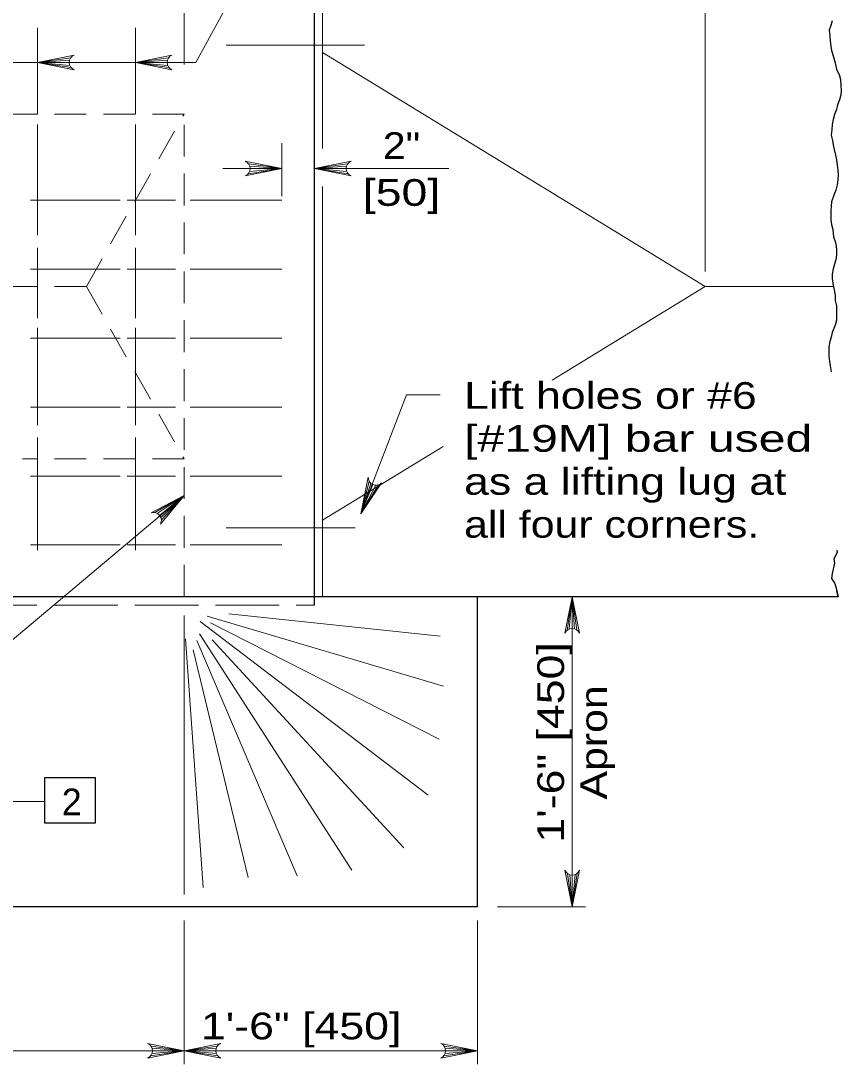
# Model space of a CAD drawing. Extents: x 339.1 to 373.1, y 1412.7 to 1456.7.
# Drawn here: x 356.2 to 360.99, y 1446.83 to 1452.93 of the extents above; entities that cross this region are included whole.
import ezdxf
from ezdxf.enums import TextEntityAlignment as Align

# ---------------------------------------------------------------- set-up
doc = ezdxf.new("R2010")
doc.units = 0
doc.header["$LTSCALE"] = 0.062
doc.linetypes.add('LONG_DASHED', pattern=[7.5, 6, -1.5])
doc.linetypes.add('MEDIUM_DASHED', pattern=[4.5, 3, -1.5])
doc.layers.add('1', color=7, linetype='Continuous', lineweight=13)

msp = doc.modelspace()

# ---------------------------------------------------------------- linework, layer by layer
at = {"layer": '1'}
for p, q in [((357.15083, 1452.67717), (357.15083, 1454.9895)), ((360.19683, 1451.46717), (360.19683, 1454.9895)), ((357.95992, 1452.18633), (357.95992, 1453.1925)), ((356.29417, 1452.38633), (356.29417, 1452.89025)), ((356.86533, 1452.38633), (356.86533, 1452.89025)), ((357.39633, 1452.78942), (358.20542, 1452.78942)), ((356.48808, 1452.71575), (356.29417, 1452.68867)), ((356.4815, 1452.70233), (356.29417, 1452.68867)), ((357.05917, 1452.71575), (356.86533, 1452.68867)), ((357.05258, 1452.70233), (356.86533, 1452.68867)), ((359.76317, 1451.64367), (357.95992, 1452.74608)), ((356.4795, 1452.68867), (356.29417, 1452.68867)), ((356.48292, 1452.67125), (356.29417, 1452.68867)), ((356.49033, 1452.65867), (356.29417, 1452.68867)), ((357.05058, 1452.68867), (356.86533, 1452.68867)), ((357.05408, 1452.67125), (356.86533, 1452.68867)), ((357.0615, 1452.65867), (356.86533, 1452.68867)), ((356.29417, 1451.67858), (356.29417, 1452.32525)), ((356.86533, 1451.67858), (356.86533, 1452.32525)), ((357.722, 1451.90667), (357.722, 1452.2175)), ((357.52808, 1452.09525), (357.722, 1452.06808)), ((357.53467, 1452.08183), (357.722, 1452.06808)), ((358.10625, 1452.09525), (357.91233, 1452.06808)), ((358.09967, 1452.08183), (357.91233, 1452.06808)), ((357.37617, 1452.06808), (357.722, 1452.06808)), ((357.52583, 1452.03808), (357.722, 1452.06808)), ((357.53325, 1452.05067), (357.722, 1452.06808)), ((357.53667, 1452.06808), (357.722, 1452.06808)), ((357.91233, 1452.06808), (358.69775, 1452.06808)), ((358.09767, 1452.06808), (357.91233, 1452.06808)), ((358.10108, 1452.05067), (357.91233, 1452.06808)), ((358.1085, 1452.03808), (357.91233, 1452.06808)), ((357.95992, 1449.56467), (357.95992, 1451.964)), ((356.77733, 1451.88242), (356.2535, 1451.88242)), ((357.09992, 1451.88242), (356.81767, 1451.88242)), ((357.18508, 1451.88242), (357.722, 1451.88242)), ((356.29417, 1451.19358), (356.29417, 1451.6055)), ((356.86533, 1451.19358), (356.86533, 1451.6055)), ((360.19683, 1451.37858), (359.76317, 1451.64367)), ((356.77733, 1451.47933), (356.2535, 1451.47933)), ((357.09992, 1451.47933), (356.81767, 1451.47933)), ((357.18508, 1451.47933), (357.722, 1451.47933)), ((360.19683, 1451.37858), (359.76008, 1451.11158)), ((360.19683, 1451.37858), (360.94533, 1451.37858)), ((356.29417, 1450.56767), (356.29417, 1451.13608)), ((356.86533, 1450.56767), (356.86533, 1451.13608)), ((359.76008, 1451.11158), (359.30133, 1450.83092)), ((356.77733, 1451.07625), (356.2535, 1451.07625)), ((357.09992, 1451.07625), (356.81767, 1451.07625)), ((357.18508, 1451.07625), (357.722, 1451.07625)), ((356.77733, 1450.67317), (356.2535, 1450.67317)), ((357.09992, 1450.67317), (356.81767, 1450.67317)), ((357.18508, 1450.67317), (357.722, 1450.67317)), ((356.29417, 1449.8375), (356.29417, 1450.49467)), ((356.86533, 1449.8375), (356.86533, 1450.49467)), ((358.66542, 1450.44242), (357.95992, 1450.01133)), ((356.77733, 1450.27008), (356.2535, 1450.27008)), ((357.09992, 1450.27008), (356.81767, 1450.27008)), ((357.18508, 1450.27008), (357.722, 1450.27008)), ((358.23217, 1450.23808), (358.1825, 1450.04875)), ((358.242, 1450.22692), (358.1825, 1450.04875)), ((358.25392, 1450.21975), (358.1825, 1450.04875)), ((358.28575, 1450.21825), (358.1825, 1450.04875)), ((358.27125, 1450.21625), (358.1825, 1450.04875)), ((356.97983, 1450.05625), (357.15083, 1450.157)), ((356.99358, 1450.05125), (357.15083, 1450.157)), ((357.00717, 1450.03992), (357.15083, 1450.157)), ((357.01433, 1450.028), (357.15083, 1450.157)), ((357.01775, 1450.01342), (357.15083, 1450.157)), ((356.77733, 1449.86692), (356.2535, 1449.86692)), ((357.09992, 1449.86692), (356.81767, 1449.86692)), ((357.18508, 1449.86692), (357.722, 1449.86692)), ((359.38842, 1449.36842), (359.41842, 1449.56467)), ((359.401, 1449.37583), (359.41842, 1449.56467)), ((359.41842, 1447.75067), (359.41842, 1449.56467)), ((359.41842, 1449.37933), (359.41842, 1449.56467)), ((359.43208, 1449.37733), (359.41842, 1449.56467)), ((359.4455, 1449.37075), (359.41842, 1449.56467)), ((358.64683, 1449.33425), (357.41192, 1449.46475)), ((357.15083, 1447.82367), (357.15083, 1449.45425)), ((358.57633, 1448.40492), (357.24375, 1449.41883)), ((358.66667, 1449.04042), (357.28467, 1449.45167)), ((358.64075, 1448.73142), (357.30383, 1449.41267)), ((357.23967, 1449.34808), (358.13033, 1447.96567)), ((357.15875, 1449.31792), (357.26192, 1447.86433)), ((357.225, 1449.30858), (357.81183, 1447.93217)), ((357.31367, 1449.31142), (358.43408, 1448.096)), ((357.20367, 1449.25483), (357.52425, 1447.92333)), ((359.39125, 1447.94458), (359.41842, 1447.75067)), ((359.40467, 1447.938), (359.41842, 1447.75067)), ((359.44842, 1447.94683), (359.41842, 1447.75067)), ((359.43583, 1447.93942), (359.41842, 1447.75067)), ((359.41842, 1447.936), (359.41842, 1447.75067)), ((358.98208, 1447.75067), (359.49708, 1447.75067)), ((357.15083, 1447.67167), (357.15083, 1446.83117)), ((358.86425, 1447.67167), (358.86425, 1446.83117)), ((356.95467, 1446.87983), (357.15083, 1446.90983)), ((356.957, 1446.937), (357.15083, 1446.90983)), ((356.96208, 1446.89242), (357.15083, 1446.90983)), ((356.9635, 1446.92358), (357.15083, 1446.90983)), ((356.9655, 1446.90983), (357.15083, 1446.90983)), ((357.34475, 1446.937), (357.15083, 1446.90983)), ((357.33817, 1446.92358), (357.15083, 1446.90983)), ((358.86425, 1446.90983), (357.15083, 1446.90983)), ((357.33617, 1446.90983), (357.15083, 1446.90983)), ((357.33958, 1446.89242), (357.15083, 1446.90983)), ((357.347, 1446.87983), (357.15083, 1446.90983)), ((358.668, 1446.87983), (358.86425, 1446.90983)), ((358.67033, 1446.937), (358.86425, 1446.90983)), ((358.6755, 1446.89242), (358.86425, 1446.90983)), ((358.67692, 1446.92358), (358.86425, 1446.90983)), ((358.67892, 1446.90983), (358.86425, 1446.90983))]:
    msp.add_line(p, q, dxfattribs=at)
at = {"layer": '1', "linetype": 'MEDIUM_DASHED'}
for p, q in [((357.15083, 1452.38633), (345.68083, 1452.38633)), ((356.57975, 1451.37858), (357.15083, 1452.38633)), ((357.15083, 1449.56467), (357.15083, 1452.38633)), ((356.57975, 1451.37858), (353.80425, 1451.37858)), ((356.57975, 1451.37858), (357.15083, 1450.37083)), ((357.15083, 1450.37083), (356.20625, 1450.37083))]:
    msp.add_line(p, q, dxfattribs=at)
at = {"layer": '1', "lineweight": 25}
for p, q in [((360.97275, 1449.56467), (343.61608, 1449.56467)), ((358.86425, 1447.75067), (358.86425, 1449.56467)), ((358.86425, 1447.75067), (353.90383, 1447.75067))]:
    msp.add_line(p, q, dxfattribs=at)
at = {"layer": '1', "linetype": 'LONG_DASHED'}
msp.add_line((345.06217, 1449.51425), (357.91233, 1449.51425), dxfattribs=at)
at = {"layer": '1'}
for points in [[(357.219, 1452.68867), (357.70825, 1453.58567), (358.31458, 1453.58567)], [(356.50833, 1452.64583), (356.29417, 1452.68867), (356.50833, 1452.7315)], [(357.0795, 1452.64583), (356.86533, 1452.68867), (357.0795, 1452.7315)], [(357.219, 1452.68867), (356.86533, 1452.68867), (356.29417, 1452.68867), (355.72308, 1452.68867)], [(357.50783, 1452.02525), (357.722, 1452.06808), (357.50783, 1452.11092)], [(358.1265, 1452.02525), (357.91233, 1452.06808), (358.1265, 1452.11092)], [(358.1825, 1450.04875), (358.45, 1450.74492), (358.64667, 1450.74492)], [(358.3045, 1450.22992), (358.1825, 1450.04875), (358.2255, 1450.26292)], [(357.15083, 1450.157), (355.54258, 1448.80458), (355.22842, 1448.80458)], [(356.95775, 1450.05483), (357.15083, 1450.157), (357.01192, 1449.98842)], [(357.39633, 1449.96775), (357.49008, 1449.96775), (358.14992, 1449.96775)], [(359.37558, 1449.3505), (359.41842, 1449.56467), (359.46125, 1449.3505)], [(355.27908, 1447.7505), (356.0625, 1448.36683), (356.33358, 1448.36683)], [(359.46125, 1447.96483), (359.41842, 1447.75067), (359.37558, 1447.96483)], [(357.15083, 1446.90983), (352.38625, 1446.90983), (345.82367, 1446.90983)], [(356.93667, 1446.867), (357.15083, 1446.90983), (356.93667, 1446.95267)], [(357.365, 1446.867), (357.15083, 1446.90983), (357.365, 1446.95267)], [(358.65008, 1446.867), (358.86425, 1446.90983), (358.65008, 1446.95267)]]:
    msp.add_lwpolyline(points, dxfattribs=at)
at = {"layer": '1', "lineweight": 25}
for points in [[(357.91233, 1449.51425), (357.91233, 1453.1925), (343.58617, 1453.1925)], [(360.93858, 1452.93225), (360.92958, 1452.904), (360.92075, 1452.87708), (360.92458, 1452.84342), (360.92583, 1452.8125), (360.92958, 1452.78433), (360.93475, 1452.75867), (360.94358, 1452.72775), (360.955, 1452.68617), (360.964, 1452.64717), (360.97917, 1452.61892), (360.98683, 1452.588), (360.98942, 1452.55567), (360.99058, 1452.52467), (360.98808, 1452.49917), (360.98175, 1452.46958), (360.969, 1452.44133), (360.96267, 1452.41442), (360.95258, 1452.3835), (360.94358, 1452.35533), (360.93733, 1452.32567), (360.936, 1452.29475), (360.93217, 1452.26392), (360.93983, 1452.23292), (360.94358, 1452.20608), (360.95, 1452.17917), (360.95758, 1452.14692), (360.964, 1452.11858), (360.96775, 1452.08908), (360.97158, 1452.05942), (360.97283, 1452.03392), (360.97158, 1452.00158), (360.96775, 1451.97208), (360.95883, 1451.94108), (360.94875, 1451.91292), (360.9335, 1451.87392), (360.93217, 1451.84833), (360.93092, 1451.82008), (360.93092, 1451.79317), (360.93092, 1451.76758), (360.93475, 1451.74067), (360.94117, 1451.71117), (360.94617, 1451.66808), (360.95633, 1451.6425), (360.96142, 1451.617), (360.96267, 1451.59142), (360.96267, 1451.56317), (360.95883, 1451.535), (360.95258, 1451.50942), (360.94358, 1451.4825), (360.93858, 1451.45158), (360.93858, 1451.42608), (360.94492, 1451.38433), (360.95, 1451.35875), (360.955, 1451.3265), (360.95633, 1451.29692), (360.96267, 1451.266), (360.964, 1451.23642), (360.964, 1451.21075), (360.964, 1451.18125), (360.95633, 1451.15167), (360.93733, 1451.11), (360.93217, 1451.08308), (360.92458, 1451.0575), (360.91817, 1451.02525), (360.91817, 1450.99967), (360.9195, 1450.97142), (360.92333, 1450.9405), (360.92717, 1450.915), (360.93325, 1450.87867)], [(360.966, 1449.83633), (360.96775, 1449.823), (360.94875, 1449.78533), (360.95125, 1449.75975), (360.94492, 1449.72617), (360.93733, 1449.70058), (360.93475, 1449.67108), (360.95375, 1449.64142), (360.96142, 1449.6145), (360.97275, 1449.56467), (360.96642, 1449.59967)]]:
    msp.add_lwpolyline(points, dxfattribs=at)
msp.add_lwpolyline([(356.33358, 1448.50467), (356.33358, 1448.24292), (356.63225, 1448.24292), (356.63225, 1448.50467)], close=True, dxfattribs=at)
at = {"layer": '1'}
for centre, start, end in [((356.52564, 1452.68871), 112.08782, 247.91395), ((357.09676, 1452.68871), 112.08782, 247.91395), ((357.49051, 1452.06814), 292.08605, 67.91218), ((358.14381, 1452.06814), 112.08782, 247.91395), ((358.27163, 1450.26236), 179.42821, 315.25434), ((356.97148, 1450.01069), 331.27463, 107.10076), ((359.41844, 1449.33316), 22.08782, 157.91395), ((359.41834, 1447.98214), 202.08782, 337.91395), ((356.91939, 1446.9099), 292.08605, 67.91218), ((357.38232, 1446.9099), 112.08782, 247.91395), ((358.63275, 1446.9099), 292.08605, 67.91218)]:
    msp.add_arc(centre, 0.04623, start, end, dxfattribs=at)

# ---------------------------------------------------------------- texts
for s, width, p in [('2"', 1.15, (358.42117, 1452.12425)), ('[50]', 1.3, (358.42125, 1451.85025))]:
    msp.add_text(s, height=0.156, dxfattribs=dict(at, width=width)).set_placement(p, align=Align.CENTER)
for s, width, p in [('Lift holes or #6', 1.25, (358.78683, 1450.66317)), ('[#19M] bar used', 1.35, (358.78683, 1450.412)), ('as a lifting lug at', 1.25, (358.78683, 1450.16083)), ('all four corners.', 1.2, (358.78683, 1449.90967)), ('1\'-6" [450]', 1.25, (357.24858, 1446.97625))]:
    msp.add_text(s, height=0.156, dxfattribs=dict(at, width=width)).set_placement(p)
for s, width, p in [('1\'-6" [450]', 1.25, (359.37083, 1448.71246)), ('Apron', 1.2, (359.622, 1448.71237))]:
    msp.add_text(s, height=0.156, rotation=90, dxfattribs=dict(at, width=width)).set_placement(p, align=Align.CENTER)
msp.add_text('2', height=0.156, dxfattribs=at).set_placement((356.4355, 1448.2865))

doc.saveas('drawing.dxf')
